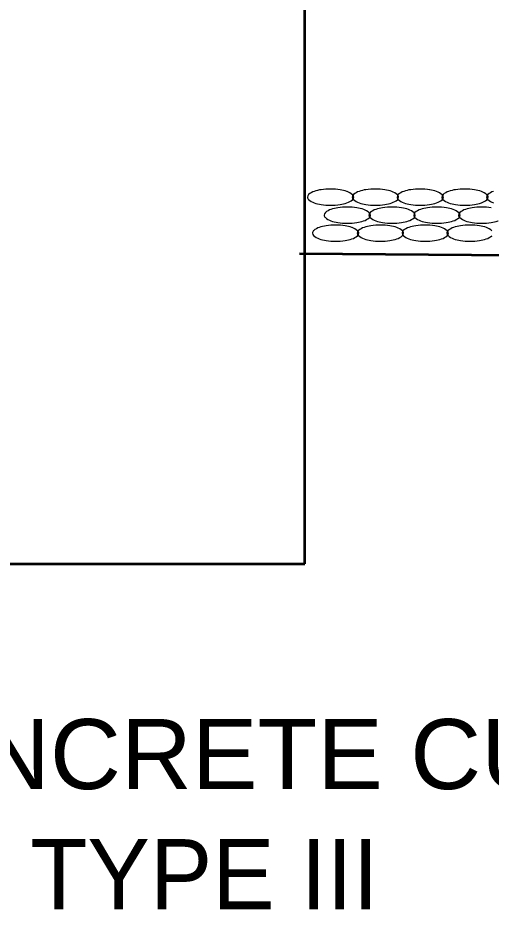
# Model space of a CAD drawing. Extents: x 36.6 to 71.9, y 0.8 to 22.8.
# Drawn here: x 56.573 to 57.63, y 6.393 to 8.381 of the extents above; entities that cross this region are included whole.
import ezdxf

# ---------------------------------------------------------------- set-up
doc = ezdxf.new("R2010")
doc.units = 0
doc.header["$LTSCALE"] = 0.062
doc.layers.add('1', color=7, linetype='Continuous', lineweight=13)
doc.layers.add('3', color=7, linetype='Continuous', lineweight=25)

msp = doc.modelspace()

# ---------------------------------------------------------------- linework, layer by layer
at = {"layer": '1', "lineweight": 53}
for p, q in [((57.21408, 7.16325), (57.21408, 9.45767)), ((58.56083, 7.845), (57.20167, 7.85417)), ((55.94492, 7.16325), (57.21408, 7.16325))]:
    msp.add_line(p, q, dxfattribs=at)
at = {"layer": '3'}
for centre, radius, start, end in [((57.24792, 7.95633), 0.03973, 109.38073, 130.27344), ((57.26142, 7.91583), 0.08246, 97.86464, 108.89243), ((57.27117, 7.85125), 0.14771, 89.93461, 98.17249), ((57.27092, 7.85183), 0.14718, 81.58628, 89.82415), ((57.28025, 7.91567), 0.08267, 70.52275, 81.55054), ((57.29467, 7.95608), 0.03973, 49.72656, 70.61927), ((57.34792, 7.95633), 0.03973, 109.38073, 130.27344), ((57.36142, 7.91583), 0.08246, 97.86464, 108.89243), ((57.37117, 7.85125), 0.14771, 89.93461, 98.17249), ((57.37092, 7.85183), 0.14718, 81.58628, 89.82415), ((57.38025, 7.91567), 0.08267, 70.52275, 81.55054), ((57.39467, 7.95608), 0.03973, 49.72656, 70.61927), ((57.44792, 7.95633), 0.03973, 109.38073, 130.27344), ((57.46142, 7.91583), 0.08246, 97.86464, 108.89243), ((57.47117, 7.85125), 0.14771, 89.93461, 98.17249), ((57.47092, 7.85183), 0.14718, 81.58628, 89.82415), ((57.48025, 7.91567), 0.08267, 70.52275, 81.55054), ((57.49467, 7.95608), 0.03973, 49.72656, 70.61927), ((57.54792, 7.95633), 0.03973, 109.38073, 130.27344), ((57.56142, 7.91583), 0.08246, 97.86464, 108.89243), ((57.57117, 7.85125), 0.14771, 89.93461, 98.17249), ((57.57092, 7.85183), 0.14718, 81.58628, 89.82415), ((57.58025, 7.91567), 0.08267, 70.52275, 81.55054), ((57.59467, 7.95608), 0.03973, 49.72656, 70.61927), ((57.64792, 7.95633), 0.03973, 109.38073, 130.27344), ((57.22692, 7.981), 0.00734, 129.54957, 179.39103), ((57.227, 7.981), 0.00739, 179.58668, 229.42813), ((57.24783, 8.00575), 0.03973, 229.72656, 250.61927), ((57.29458, 8.0055), 0.03973, 289.38073, 310.27344), ((57.32692, 7.981), 0.00734, 129.54957, 179.39103), ((57.327, 7.981), 0.00739, 179.58668, 229.42813), ((57.31558, 7.98083), 0.00734, 309.54957, 359.39103), ((57.3155, 7.98083), 0.00739, 359.58668, 49.42813), ((57.34783, 8.00575), 0.03973, 229.72656, 250.61927), ((57.39458, 8.0055), 0.03973, 289.38073, 310.27344), ((57.42692, 7.981), 0.00734, 129.54957, 179.39103), ((57.427, 7.981), 0.00739, 179.58668, 229.42813), ((57.41558, 7.98083), 0.00734, 309.54957, 359.39103), ((57.4155, 7.98083), 0.00739, 359.58668, 49.42813), ((57.44783, 8.00575), 0.03973, 229.72656, 250.61927), ((57.49458, 8.0055), 0.03973, 289.38073, 310.27344), ((57.52692, 7.981), 0.00734, 129.54957, 179.39103), ((57.527, 7.981), 0.00739, 179.58668, 229.42813), ((57.51558, 7.98083), 0.00734, 309.54957, 359.39103), ((57.5155, 7.98083), 0.00739, 359.58668, 49.42813), ((57.54783, 8.00575), 0.03973, 229.72656, 250.61927), ((57.59458, 8.0055), 0.03973, 289.38073, 310.27344), ((57.62692, 7.981), 0.00734, 129.54957, 179.39103), ((57.627, 7.981), 0.00739, 179.58668, 229.42813), ((57.61558, 7.98083), 0.00734, 309.54957, 359.39103), ((57.6155, 7.98083), 0.00739, 359.58668, 49.42813), ((57.64783, 8.00575), 0.03973, 229.72656, 250.61927), ((57.26225, 8.04617), 0.08267, 250.52275, 261.55054), ((57.27158, 8.11), 0.14718, 261.58628, 269.82415), ((57.285, 7.91592), 0.03982, 108.92941, 129.82212), ((57.27133, 8.11058), 0.14771, 269.93461, 278.17249), ((57.29917, 7.876), 0.08214, 98.2289, 109.25669), ((57.30783, 7.81108), 0.14767, 89.71011, 97.94798), ((57.28108, 8.046), 0.08246, 277.86464, 288.89243), ((57.30817, 7.811), 0.14776, 81.60312, 89.841), ((57.31758, 7.87583), 0.08224, 70.44986, 81.47765), ((57.36225, 8.04617), 0.08267, 250.52275, 261.55054), ((57.33192, 7.91583), 0.03973, 49.72656, 70.61927), ((57.37158, 8.11), 0.14718, 261.58628, 269.82415), ((57.385, 7.91592), 0.03982, 108.92941, 129.82212), ((57.37133, 8.11058), 0.14771, 269.93461, 278.17249), ((57.39917, 7.876), 0.08214, 98.2289, 109.25669), ((57.40783, 7.81108), 0.14767, 89.71011, 97.94798), ((57.38108, 8.046), 0.08246, 277.86464, 288.89243), ((57.40817, 7.811), 0.14776, 81.60312, 89.841), ((57.41758, 7.87583), 0.08224, 70.44986, 81.47765), ((57.46225, 8.04617), 0.08267, 250.52275, 261.55054), ((57.43192, 7.91583), 0.03973, 49.72656, 70.61927), ((57.47158, 8.11), 0.14718, 261.58628, 269.82415), ((57.485, 7.91592), 0.03982, 108.92941, 129.82212), ((57.47133, 8.11058), 0.14771, 269.93461, 278.17249), ((57.49917, 7.876), 0.08214, 98.2289, 109.25669), ((57.50783, 7.81108), 0.14767, 89.71011, 97.94798), ((57.48108, 8.046), 0.08246, 277.86464, 288.89243), ((57.50817, 7.811), 0.14776, 81.60312, 89.841), ((57.51758, 7.87583), 0.08224, 70.44986, 81.47765), ((57.56225, 8.04617), 0.08267, 250.52275, 261.55054), ((57.53192, 7.91583), 0.03973, 49.72656, 70.61927), ((57.57158, 8.11), 0.14718, 261.58628, 269.82415), ((57.585, 7.91592), 0.03982, 108.92941, 129.82212), ((57.57133, 8.11058), 0.14771, 269.93461, 278.17249), ((57.59917, 7.876), 0.08214, 98.2289, 109.25669), ((57.60783, 7.81108), 0.14767, 89.71011, 97.94798), ((57.58108, 8.046), 0.08246, 277.86464, 288.89243), ((57.60817, 7.811), 0.14776, 81.60312, 89.841), ((57.26433, 7.94083), 0.00739, 179.58668, 229.42813), ((57.26425, 7.94092), 0.0073, 130.24992, 180.09138), ((57.28517, 7.96558), 0.03973, 229.72656, 250.61927), ((57.33208, 7.9655), 0.03982, 288.92941, 309.82212), ((57.36433, 7.94083), 0.00739, 179.58668, 229.42813), ((57.36425, 7.94092), 0.0073, 130.24992, 180.09138), ((57.35283, 7.94058), 0.0073, 359.90862, 49.75007), ((57.35275, 7.9405), 0.00739, 310.57186, 0.41332), ((57.38517, 7.96558), 0.03973, 229.72656, 250.61927), ((57.43208, 7.9655), 0.03982, 288.92941, 309.82212), ((57.46433, 7.94083), 0.00739, 179.58668, 229.42813), ((57.46425, 7.94092), 0.0073, 130.24992, 180.09138), ((57.45283, 7.94058), 0.0073, 359.90862, 49.75007), ((57.45275, 7.9405), 0.00739, 310.57186, 0.41332), ((57.48517, 7.96558), 0.03973, 229.72656, 250.61927), ((57.53208, 7.9655), 0.03982, 288.92941, 309.82212), ((57.56433, 7.94083), 0.00739, 179.58668, 229.42813), ((57.56425, 7.94092), 0.0073, 130.24992, 180.09138), ((57.55283, 7.94058), 0.0073, 359.90862, 49.75007), ((57.55275, 7.9405), 0.00739, 310.57186, 0.41332), ((57.58517, 7.96558), 0.03973, 229.72656, 250.61927), ((57.25892, 7.876), 0.03962, 109.09243, 129.98513), ((57.27258, 7.83542), 0.08246, 97.86464, 108.89243), ((57.28233, 7.77083), 0.14771, 89.93461, 98.17249), ((57.2995, 8.00558), 0.08224, 250.44986, 261.47765), ((57.28208, 7.77142), 0.14718, 81.58628, 89.82415), ((57.30892, 8.07042), 0.14776, 261.60312, 269.841), ((57.29142, 7.83525), 0.08267, 70.52275, 81.55054), ((57.30917, 8.06975), 0.1471, 269.7252, 277.96307), ((57.30583, 7.87567), 0.03973, 49.72656, 70.61927), ((57.31783, 8.00583), 0.08256, 278.15741, 289.1852), ((57.35892, 7.876), 0.03962, 109.09243, 129.98513), ((57.37258, 7.83542), 0.08246, 97.86464, 108.89243), ((57.38233, 7.77083), 0.14771, 89.93461, 98.17249), ((57.3995, 8.00558), 0.08224, 250.44986, 261.47765), ((57.38208, 7.77142), 0.14718, 81.58628, 89.82415), ((57.40892, 8.07042), 0.14776, 261.60312, 269.841), ((57.39142, 7.83525), 0.08267, 70.52275, 81.55054), ((57.40917, 8.06975), 0.1471, 269.7252, 277.96307), ((57.40583, 7.87567), 0.03973, 49.72656, 70.61927), ((57.41783, 8.00583), 0.08256, 278.15741, 289.1852), ((57.45892, 7.876), 0.03962, 109.09243, 129.98513), ((57.47258, 7.83542), 0.08246, 97.86464, 108.89243), ((57.48233, 7.77083), 0.14771, 89.93461, 98.17249), ((57.4995, 8.00558), 0.08224, 250.44986, 261.47765), ((57.48208, 7.77142), 0.14718, 81.58628, 89.82415), ((57.50892, 8.07042), 0.14776, 261.60312, 269.841), ((57.49142, 7.83525), 0.08267, 70.52275, 81.55054), ((57.50917, 8.06975), 0.1471, 269.7252, 277.96307), ((57.50583, 7.87567), 0.03973, 49.72656, 70.61927), ((57.51783, 8.00583), 0.08256, 278.15741, 289.1852), ((57.55892, 7.876), 0.03962, 109.09243, 129.98513), ((57.57258, 7.83542), 0.08246, 97.86464, 108.89243), ((57.58233, 7.77083), 0.14771, 89.93461, 98.17249), ((57.5995, 8.00558), 0.08224, 250.44986, 261.47765), ((57.58208, 7.77142), 0.14718, 81.58628, 89.82415), ((57.60892, 8.07042), 0.14776, 261.60312, 269.841), ((57.59142, 7.83525), 0.08267, 70.52275, 81.55054), ((57.60917, 8.06975), 0.1471, 269.7252, 277.96307), ((57.60583, 7.87567), 0.03973, 49.72656, 70.61927), ((57.61783, 8.00583), 0.08256, 278.15741, 289.1852), ((57.23817, 7.90067), 0.00743, 129.87815, 179.7196), ((57.23808, 7.90067), 0.0073, 179.90862, 229.75007), ((57.25925, 7.92533), 0.03985, 229.43991, 250.33262), ((57.30592, 7.92508), 0.03962, 289.09243, 309.98513), ((57.33817, 7.90067), 0.00743, 129.87815, 179.7196), ((57.33808, 7.90067), 0.0073, 179.90862, 229.75007), ((57.32675, 7.90042), 0.00734, 309.54957, 359.39103), ((57.32667, 7.90042), 0.00739, 359.58668, 49.42813), ((57.35925, 7.92533), 0.03985, 229.43991, 250.33262), ((57.40592, 7.92508), 0.03962, 289.09243, 309.98513), ((57.43817, 7.90067), 0.00743, 129.87815, 179.7196), ((57.43808, 7.90067), 0.0073, 179.90862, 229.75007), ((57.42675, 7.90042), 0.00734, 309.54957, 359.39103), ((57.42667, 7.90042), 0.00739, 359.58668, 49.42813), ((57.45925, 7.92533), 0.03985, 229.43991, 250.33262), ((57.50592, 7.92508), 0.03962, 289.09243, 309.98513), ((57.53817, 7.90067), 0.00743, 129.87815, 179.7196), ((57.53808, 7.90067), 0.0073, 179.90862, 229.75007), ((57.52675, 7.90042), 0.00734, 309.54957, 359.39103), ((57.52667, 7.90042), 0.00739, 359.58668, 49.42813), ((57.55925, 7.92533), 0.03985, 229.43991, 250.33262), ((57.60592, 7.92508), 0.03962, 289.09243, 309.98513), ((57.273, 7.96583), 0.08256, 250.81479, 261.84259), ((57.28275, 8.02967), 0.14718, 261.58628, 269.82415), ((57.28308, 8.03017), 0.14767, 269.71011, 277.94798), ((57.29175, 7.96567), 0.08256, 278.15741, 289.1852), ((57.373, 7.96583), 0.08256, 250.81479, 261.84259), ((57.38275, 8.02967), 0.14718, 261.58628, 269.82415), ((57.38308, 8.03017), 0.14767, 269.71011, 277.94798), ((57.39175, 7.96567), 0.08256, 278.15741, 289.1852), ((57.473, 7.96583), 0.08256, 250.81479, 261.84259), ((57.48275, 8.02967), 0.14718, 261.58628, 269.82415), ((57.48308, 8.03017), 0.14767, 269.71011, 277.94798), ((57.49175, 7.96567), 0.08256, 278.15741, 289.1852), ((57.573, 7.96583), 0.08256, 250.81479, 261.84259), ((57.58275, 8.02967), 0.14718, 261.58628, 269.82415), ((57.58308, 8.03017), 0.14767, 269.71011, 277.94798), ((57.59175, 7.96567), 0.08256, 278.15741, 289.1852)]:
    msp.add_arc(centre, radius, start, end, dxfattribs=at)
at = {"layer": '3', "lineweight": 13}
for centre, radius, start, end in [((57.24792, 7.95633), 0.03973, 109.38073, 130.27344), ((57.26142, 7.91583), 0.08246, 97.86464, 108.89243), ((57.27117, 7.85125), 0.14771, 89.93461, 98.17249), ((57.27092, 7.85183), 0.14718, 81.58628, 89.82415), ((57.28025, 7.91567), 0.08267, 70.52275, 81.55054), ((57.29467, 7.95608), 0.03973, 49.72656, 70.61927), ((57.34792, 7.95633), 0.03973, 109.38073, 130.27344), ((57.36142, 7.91583), 0.08246, 97.86464, 108.89243), ((57.37117, 7.85125), 0.14771, 89.93461, 98.17249), ((57.37092, 7.85183), 0.14718, 81.58628, 89.82415), ((57.38025, 7.91567), 0.08267, 70.52275, 81.55054), ((57.39467, 7.95608), 0.03973, 49.72656, 70.61927), ((57.44792, 7.95633), 0.03973, 109.38073, 130.27344), ((57.46142, 7.91583), 0.08246, 97.86464, 108.89243), ((57.47117, 7.85125), 0.14771, 89.93461, 98.17249), ((57.47092, 7.85183), 0.14718, 81.58628, 89.82415), ((57.48025, 7.91567), 0.08267, 70.52275, 81.55054), ((57.49467, 7.95608), 0.03973, 49.72656, 70.61927), ((57.54792, 7.95633), 0.03973, 109.38073, 130.27344), ((57.56142, 7.91583), 0.08246, 97.86464, 108.89243), ((57.57117, 7.85125), 0.14771, 89.93461, 98.17249), ((57.57092, 7.85183), 0.14718, 81.58628, 89.82415), ((57.58025, 7.91567), 0.08267, 70.52275, 81.55054), ((57.59467, 7.95608), 0.03973, 49.72656, 70.61927), ((57.64792, 7.95633), 0.03973, 109.38073, 130.27344), ((57.22692, 7.981), 0.00734, 129.54957, 179.39103), ((57.227, 7.981), 0.00739, 179.58668, 229.42813), ((57.24783, 8.00575), 0.03973, 229.72656, 250.61927), ((57.29458, 8.0055), 0.03973, 289.38073, 310.27344), ((57.32692, 7.981), 0.00734, 129.54957, 179.39103), ((57.327, 7.981), 0.00739, 179.58668, 229.42813), ((57.31558, 7.98083), 0.00734, 309.54957, 359.39103), ((57.3155, 7.98083), 0.00739, 359.58668, 49.42813), ((57.34783, 8.00575), 0.03973, 229.72656, 250.61927), ((57.39458, 8.0055), 0.03973, 289.38073, 310.27344), ((57.42692, 7.981), 0.00734, 129.54957, 179.39103), ((57.427, 7.981), 0.00739, 179.58668, 229.42813), ((57.41558, 7.98083), 0.00734, 309.54957, 359.39103), ((57.4155, 7.98083), 0.00739, 359.58668, 49.42813), ((57.44783, 8.00575), 0.03973, 229.72656, 250.61927), ((57.49458, 8.0055), 0.03973, 289.38073, 310.27344), ((57.52692, 7.981), 0.00734, 129.54957, 179.39103), ((57.527, 7.981), 0.00739, 179.58668, 229.42813), ((57.51558, 7.98083), 0.00734, 309.54957, 359.39103), ((57.5155, 7.98083), 0.00739, 359.58668, 49.42813), ((57.54783, 8.00575), 0.03973, 229.72656, 250.61927), ((57.59458, 8.0055), 0.03973, 289.38073, 310.27344), ((57.62692, 7.981), 0.00734, 129.54957, 179.39103), ((57.627, 7.981), 0.00739, 179.58668, 229.42813), ((57.61558, 7.98083), 0.00734, 309.54957, 359.39103), ((57.6155, 7.98083), 0.00739, 359.58668, 49.42813), ((57.64783, 8.00575), 0.03973, 229.72656, 250.61927), ((57.26225, 8.04617), 0.08267, 250.52275, 261.55054), ((57.27158, 8.11), 0.14718, 261.58628, 269.82415), ((57.285, 7.91592), 0.03982, 108.92941, 129.82212), ((57.27133, 8.11058), 0.14771, 269.93461, 278.17249), ((57.29917, 7.876), 0.08214, 98.2289, 109.25669), ((57.30783, 7.81108), 0.14767, 89.71011, 97.94798), ((57.28108, 8.046), 0.08246, 277.86464, 288.89243), ((57.30817, 7.811), 0.14776, 81.60312, 89.841), ((57.31758, 7.87583), 0.08224, 70.44986, 81.47765), ((57.36225, 8.04617), 0.08267, 250.52275, 261.55054), ((57.33192, 7.91583), 0.03973, 49.72656, 70.61927), ((57.37158, 8.11), 0.14718, 261.58628, 269.82415), ((57.385, 7.91592), 0.03982, 108.92941, 129.82212), ((57.37133, 8.11058), 0.14771, 269.93461, 278.17249), ((57.39917, 7.876), 0.08214, 98.2289, 109.25669), ((57.40783, 7.81108), 0.14767, 89.71011, 97.94798), ((57.38108, 8.046), 0.08246, 277.86464, 288.89243), ((57.40817, 7.811), 0.14776, 81.60312, 89.841), ((57.41758, 7.87583), 0.08224, 70.44986, 81.47765), ((57.46225, 8.04617), 0.08267, 250.52275, 261.55054), ((57.43192, 7.91583), 0.03973, 49.72656, 70.61927), ((57.47158, 8.11), 0.14718, 261.58628, 269.82415), ((57.485, 7.91592), 0.03982, 108.92941, 129.82212), ((57.47133, 8.11058), 0.14771, 269.93461, 278.17249), ((57.49917, 7.876), 0.08214, 98.2289, 109.25669), ((57.50783, 7.81108), 0.14767, 89.71011, 97.94798), ((57.48108, 8.046), 0.08246, 277.86464, 288.89243), ((57.50817, 7.811), 0.14776, 81.60312, 89.841), ((57.51758, 7.87583), 0.08224, 70.44986, 81.47765), ((57.56225, 8.04617), 0.08267, 250.52275, 261.55054), ((57.53192, 7.91583), 0.03973, 49.72656, 70.61927), ((57.57158, 8.11), 0.14718, 261.58628, 269.82415), ((57.585, 7.91592), 0.03982, 108.92941, 129.82212), ((57.57133, 8.11058), 0.14771, 269.93461, 278.17249), ((57.59917, 7.876), 0.08214, 98.2289, 109.25669), ((57.60783, 7.81108), 0.14767, 89.71011, 97.94798), ((57.58108, 8.046), 0.08246, 277.86464, 288.89243), ((57.60817, 7.811), 0.14776, 81.60312, 89.841), ((57.26433, 7.94083), 0.00739, 179.58668, 229.42813), ((57.26425, 7.94092), 0.0073, 130.24992, 180.09138), ((57.28517, 7.96558), 0.03973, 229.72656, 250.61927), ((57.33208, 7.9655), 0.03982, 288.92941, 309.82212), ((57.36433, 7.94083), 0.00739, 179.58668, 229.42813), ((57.36425, 7.94092), 0.0073, 130.24992, 180.09138), ((57.35283, 7.94058), 0.0073, 359.90862, 49.75007), ((57.35275, 7.9405), 0.00739, 310.57186, 0.41332), ((57.38517, 7.96558), 0.03973, 229.72656, 250.61927), ((57.43208, 7.9655), 0.03982, 288.92941, 309.82212), ((57.46433, 7.94083), 0.00739, 179.58668, 229.42813), ((57.46425, 7.94092), 0.0073, 130.24992, 180.09138), ((57.45283, 7.94058), 0.0073, 359.90862, 49.75007), ((57.45275, 7.9405), 0.00739, 310.57186, 0.41332), ((57.48517, 7.96558), 0.03973, 229.72656, 250.61927), ((57.53208, 7.9655), 0.03982, 288.92941, 309.82212), ((57.56433, 7.94083), 0.00739, 179.58668, 229.42813), ((57.56425, 7.94092), 0.0073, 130.24992, 180.09138), ((57.55283, 7.94058), 0.0073, 359.90862, 49.75007), ((57.55275, 7.9405), 0.00739, 310.57186, 0.41332), ((57.58517, 7.96558), 0.03973, 229.72656, 250.61927), ((57.25892, 7.876), 0.03962, 109.09243, 129.98513), ((57.27258, 7.83542), 0.08246, 97.86464, 108.89243), ((57.28233, 7.77083), 0.14771, 89.93461, 98.17249), ((57.2995, 8.00558), 0.08224, 250.44986, 261.47765), ((57.28208, 7.77142), 0.14718, 81.58628, 89.82415), ((57.30892, 8.07042), 0.14776, 261.60312, 269.841), ((57.29142, 7.83525), 0.08267, 70.52275, 81.55054), ((57.30917, 8.06975), 0.1471, 269.7252, 277.96307), ((57.30583, 7.87567), 0.03973, 49.72656, 70.61927), ((57.31783, 8.00583), 0.08256, 278.15741, 289.1852), ((57.35892, 7.876), 0.03962, 109.09243, 129.98513), ((57.37258, 7.83542), 0.08246, 97.86464, 108.89243), ((57.38233, 7.77083), 0.14771, 89.93461, 98.17249), ((57.3995, 8.00558), 0.08224, 250.44986, 261.47765), ((57.38208, 7.77142), 0.14718, 81.58628, 89.82415), ((57.40892, 8.07042), 0.14776, 261.60312, 269.841), ((57.39142, 7.83525), 0.08267, 70.52275, 81.55054), ((57.40917, 8.06975), 0.1471, 269.7252, 277.96307), ((57.40583, 7.87567), 0.03973, 49.72656, 70.61927), ((57.41783, 8.00583), 0.08256, 278.15741, 289.1852), ((57.45892, 7.876), 0.03962, 109.09243, 129.98513), ((57.47258, 7.83542), 0.08246, 97.86464, 108.89243), ((57.48233, 7.77083), 0.14771, 89.93461, 98.17249), ((57.4995, 8.00558), 0.08224, 250.44986, 261.47765), ((57.48208, 7.77142), 0.14718, 81.58628, 89.82415), ((57.50892, 8.07042), 0.14776, 261.60312, 269.841), ((57.49142, 7.83525), 0.08267, 70.52275, 81.55054), ((57.50917, 8.06975), 0.1471, 269.7252, 277.96307), ((57.50583, 7.87567), 0.03973, 49.72656, 70.61927), ((57.51783, 8.00583), 0.08256, 278.15741, 289.1852), ((57.55892, 7.876), 0.03962, 109.09243, 129.98513), ((57.57258, 7.83542), 0.08246, 97.86464, 108.89243), ((57.58233, 7.77083), 0.14771, 89.93461, 98.17249), ((57.5995, 8.00558), 0.08224, 250.44986, 261.47765), ((57.58208, 7.77142), 0.14718, 81.58628, 89.82415), ((57.60892, 8.07042), 0.14776, 261.60312, 269.841), ((57.59142, 7.83525), 0.08267, 70.52275, 81.55054), ((57.60917, 8.06975), 0.1471, 269.7252, 277.96307), ((57.60583, 7.87567), 0.03973, 49.72656, 70.61927), ((57.61783, 8.00583), 0.08256, 278.15741, 289.1852), ((57.23817, 7.90067), 0.00743, 129.87815, 179.7196), ((57.23808, 7.90067), 0.0073, 179.90862, 229.75007), ((57.25925, 7.92533), 0.03985, 229.43991, 250.33262), ((57.30592, 7.92508), 0.03962, 289.09243, 309.98513), ((57.33817, 7.90067), 0.00743, 129.87815, 179.7196), ((57.33808, 7.90067), 0.0073, 179.90862, 229.75007), ((57.32675, 7.90042), 0.00734, 309.54957, 359.39103), ((57.32667, 7.90042), 0.00739, 359.58668, 49.42813), ((57.35925, 7.92533), 0.03985, 229.43991, 250.33262), ((57.40592, 7.92508), 0.03962, 289.09243, 309.98513), ((57.43817, 7.90067), 0.00743, 129.87815, 179.7196), ((57.43808, 7.90067), 0.0073, 179.90862, 229.75007), ((57.42675, 7.90042), 0.00734, 309.54957, 359.39103), ((57.42667, 7.90042), 0.00739, 359.58668, 49.42813), ((57.45925, 7.92533), 0.03985, 229.43991, 250.33262), ((57.50592, 7.92508), 0.03962, 289.09243, 309.98513), ((57.53817, 7.90067), 0.00743, 129.87815, 179.7196), ((57.53808, 7.90067), 0.0073, 179.90862, 229.75007), ((57.52675, 7.90042), 0.00734, 309.54957, 359.39103), ((57.52667, 7.90042), 0.00739, 359.58668, 49.42813), ((57.55925, 7.92533), 0.03985, 229.43991, 250.33262), ((57.60592, 7.92508), 0.03962, 289.09243, 309.98513), ((57.273, 7.96583), 0.08256, 250.81479, 261.84259), ((57.28275, 8.02967), 0.14718, 261.58628, 269.82415), ((57.28308, 8.03017), 0.14767, 269.71011, 277.94798), ((57.29175, 7.96567), 0.08256, 278.15741, 289.1852), ((57.373, 7.96583), 0.08256, 250.81479, 261.84259), ((57.38275, 8.02967), 0.14718, 261.58628, 269.82415), ((57.38308, 8.03017), 0.14767, 269.71011, 277.94798), ((57.39175, 7.96567), 0.08256, 278.15741, 289.1852), ((57.473, 7.96583), 0.08256, 250.81479, 261.84259), ((57.48275, 8.02967), 0.14718, 261.58628, 269.82415), ((57.48308, 8.03017), 0.14767, 269.71011, 277.94798), ((57.49175, 7.96567), 0.08256, 278.15741, 289.1852), ((57.573, 7.96583), 0.08256, 250.81479, 261.84259), ((57.58275, 8.02967), 0.14718, 261.58628, 269.82415), ((57.58308, 8.03017), 0.14767, 269.71011, 277.94798), ((57.59175, 7.96567), 0.08256, 278.15741, 289.1852)]:
    msp.add_arc(centre, radius, start, end, dxfattribs=at)

# ---------------------------------------------------------------- texts
at = {"layer": '3', "width": 1.05}
msp.add_text('PLAIN CONCRETE CURBING', height=0.1562, dxfattribs=at).set_placement((55.46258, 6.66067))
at = {"layer": '3'}
msp.add_text('TYPE III', height=0.1562, dxfattribs=at).set_placement((56.60075, 6.39283))

doc.saveas('drawing.dxf')
